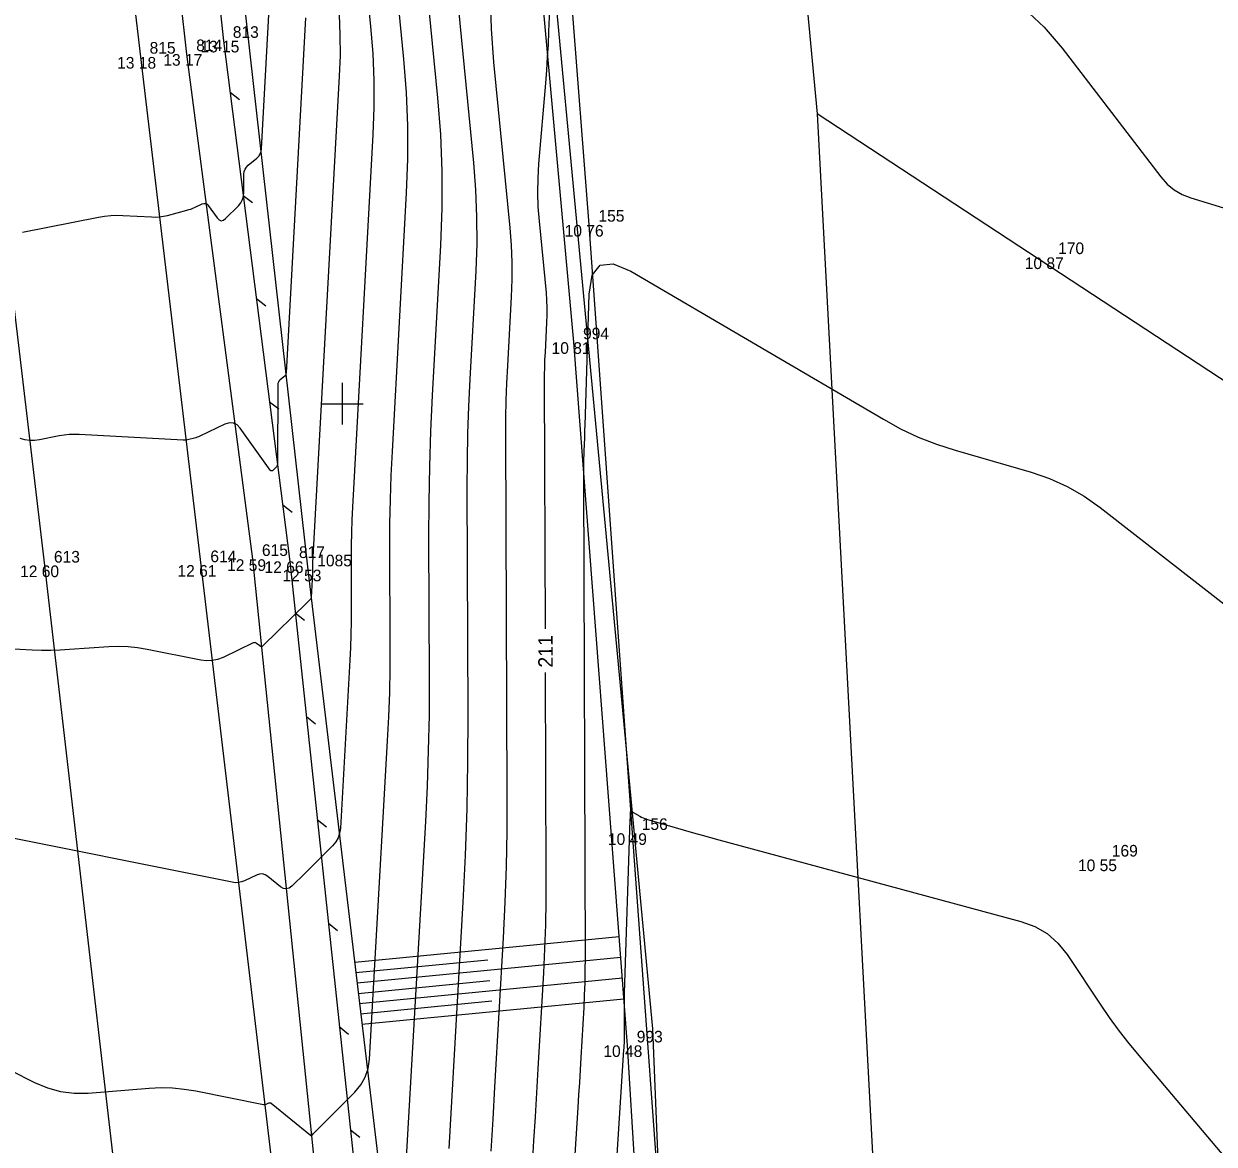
# Model space of a CAD drawing. Extents: x -711234 to -710007, y -1026313 to -1025448.
# Drawn here: x -710907.65 to -710879.04, y -1025892.81 to -1025865.86 of the extents above; entities that cross this region are included whole.
import ezdxf

# ---------------------------------------------------------------- set-up
doc = ezdxf.new("R2010")
doc.units = 0
for name, color, linetype in [('Ex_Contour Labels', 7, 'Continuous'), ('Ex_Major Contours', 7, 'Continuous'), ('Ex_Minor Contours', 7, 'Continuous'), ('Z_body', 7, 'Continuous'), ('Z_body_cisla', 7, 'Continuous'), ('Z_body_vysky_redukovane', 7, 'Continuous'), ('Z_hektometricka_sit', 7, 'Continuous'), ('Z_hrany_paty', 7, 'Continuous'), ('Z_katastr_hranice', 7, 'Continuous'), ('Z_komunikace', 7, 'Continuous'), ('Z_pole_rozhranni', 7, 'Continuous'), ('Z_svodidla', 7, 'Continuous'), ('Z_svodidla_znacky', 7, 'Continuous'), ('Z_technicke_srafy', 7, 'Continuous'), ('Z_vdz12_plna', 7, 'Continuous'), ('Z_vdz12_prerusovana', 7, 'Continuous'), ('Z_vdz25_plna', 7, 'Continuous')]:
    doc.layers.add(name, color=color, linetype=linetype)

# ---------------------------------------------------------------- blocks, each defined once
blk = doc.blocks.new('POINT_DISPLAY')
blk.add_line((0, 0), (0, 0))
blk = doc.blocks.new('Z529')
blk.add_line((0, 0), (0.2, 0.2))

msp = doc.modelspace()

# ---------------------------------------------------------------- linework, layer by layer
at = {"layer": 'Ex_Major Contours'}
for points in [[(-710909.71, -1025890.152), (-710907.396, -1025891.324), (-710907.088, -1025891.455), (-710906.771, -1025891.541), (-710906.445, -1025891.582), (-710906.11, -1025891.577), (-710904.638, -1025891.46), (-710904.356, -1025891.447), (-710904.076, -1025891.454), (-710903.797, -1025891.481), (-710903.52, -1025891.527), (-710901.891, -1025891.854), (-710901.874, -1025891.856), (-710901.858, -1025891.855), (-710901.841, -1025891.852), (-710901.826, -1025891.845), (-710901.762, -1025891.815), (-710901.747, -1025891.81), (-710901.732, -1025891.81), (-710901.718, -1025891.814), (-710901.704, -1025891.822), (-710900.759, -1025892.591), (-710900.751, -1025892.596), (-710900.742, -1025892.598), (-710900.734, -1025892.595), (-710900.726, -1025892.589), (-710900.687, -1025892.551), (-710900.671, -1025892.535), (-710900.663, -1025892.527), (-710899.698, -1025891.555), (-710899.553, -1025891.382), (-710899.446, -1025891.193), (-710899.376, -1025890.986), (-710899.344, -1025890.763), (-710898.908, -1025883.107), (-710898.879, -1025882.527), (-710898.859, -1025881.947), (-710898.848, -1025881.367), (-710898.846, -1025880.787), (-710898.854, -1025878.465), (-710898.852, -1025877.885), (-710898.841, -1025877.305), (-710898.822, -1025876.725), (-710898.794, -1025876.145), (-710898.452, -1025869.926), (-710898.423, -1025869.121), (-710898.425, -1025868.317), (-710898.457, -1025867.513), (-710898.52, -1025866.711), (-710898.947, -1025862.338)], [(-710907.682, -1025870.871), (-710905.856, -1025870.512), (-710905.711, -1025870.488), (-710905.566, -1025870.474), (-710905.42, -1025870.468), (-710905.273, -1025870.471), (-710904.587, -1025870.508), (-710904.49, -1025870.51), (-710904.394, -1025870.504), (-710904.298, -1025870.49), (-710904.203, -1025870.469), (-710903.733, -1025870.346), (-710903.685, -1025870.332), (-710903.638, -1025870.317), (-710903.592, -1025870.299), (-710903.547, -1025870.278), (-710903.367, -1025870.194), (-710903.324, -1025870.18), (-710903.285, -1025870.182), (-710903.25, -1025870.199), (-710903.219, -1025870.232), (-710903.004, -1025870.53), (-710902.958, -1025870.579), (-710902.909, -1025870.597), (-710902.857, -1025870.587), (-710902.804, -1025870.546), (-710902.496, -1025870.237), (-710902.438, -1025870.166), (-710902.396, -1025870.089), (-710902.371, -1025870.005), (-710902.363, -1025869.914), (-710902.362, -1025869.482), (-710902.355, -1025869.418), (-710902.335, -1025869.36), (-710902.303, -1025869.308), (-710902.258, -1025869.262), (-710902.051, -1025869.09), (-710902.005, -1025869.044), (-710901.971, -1025868.992), (-710901.949, -1025868.934), (-710901.94, -1025868.87), (-710901.689, -1025864.314)], [(-710895.115, -1025880.412), (-710895.136, -1025874.484), (-710895.135, -1025874.304), (-710895.132, -1025874.124), (-710895.126, -1025873.945), (-710895.117, -1025873.765), (-710895.078, -1025873.048), (-710895.071, -1025872.869), (-710895.072, -1025872.689), (-710895.079, -1025872.51), (-710895.093, -1025872.331), (-710895.261, -1025870.612), (-710895.287, -1025870.265), (-710895.297, -1025869.919), (-710895.292, -1025869.572), (-710895.271, -1025869.226), (-710895.109, -1025867.289), (-710895.084, -1025866.978), (-710895.063, -1025866.667), (-710895.045, -1025866.357), (-710895.03, -1025866.046), (-710894.978, -1025864.801)], [(-710883.607, -1025865.495), (-710883.129, -1025865.943), (-710882.697, -1025866.447), (-710880.323, -1025869.545), (-710880.172, -1025869.715), (-710880.001, -1025869.855), (-710879.81, -1025869.966), (-710879.599, -1025870.048), (-710878.714, -1025870.318)], [(-710895.427, -1025893.301), (-710895.391, -1025892.724), (-710895.356, -1025892.147), (-710895.321, -1025891.569), (-710895.288, -1025890.992), (-710895.156, -1025888.683), (-710895.128, -1025888.105), (-710895.108, -1025887.528), (-710895.097, -1025886.95), (-710895.095, -1025886.372), (-710895.112, -1025881.462)]]:
    msp.add_lwpolyline(points, dxfattribs=at)
at = {"layer": 'Ex_Minor Contours'}
for points in [[(-710897.432, -1025892.913), (-710897.095, -1025886.99), (-710897.039, -1025885.864), (-710897, -1025884.737), (-710896.979, -1025883.61), (-710896.974, -1025882.482), (-710896.993, -1025877.019), (-710896.99, -1025876.367), (-710896.978, -1025875.715), (-710896.957, -1025875.063), (-710896.926, -1025874.411), (-710896.782, -1025871.805), (-710896.759, -1025871.154), (-710896.76, -1025870.503), (-710896.786, -1025869.853), (-710896.838, -1025869.203), (-710897.575, -1025861.661)], [(-710898.261, -1025861.999), (-710897.71, -1025867.64), (-710897.64, -1025868.525), (-710897.605, -1025869.41), (-710897.603, -1025870.297), (-710897.635, -1025871.184), (-710897.834, -1025874.804), (-710897.875, -1025875.657), (-710897.903, -1025876.51), (-710897.918, -1025877.364), (-710897.922, -1025878.218), (-710897.91, -1025881.634), (-710897.913, -1025882.488), (-710897.93, -1025883.342), (-710897.959, -1025884.195), (-710898.001, -1025885.048), (-710898.533, -1025894.389)], [(-710899.634, -1025862.676), (-710899.316, -1025865.926), (-710899.265, -1025866.574), (-710899.239, -1025867.223), (-710899.238, -1025867.873), (-710899.261, -1025868.523), (-710899.754, -1025877.487), (-710899.769, -1025877.793), (-710899.779, -1025878.1), (-710899.785, -1025878.406), (-710899.786, -1025878.713), (-710899.782, -1025879.939), (-710899.783, -1025880.246), (-710899.789, -1025880.552), (-710899.799, -1025880.859), (-710899.815, -1025881.165), (-710900.045, -1025885.21), (-710900.062, -1025885.328), (-710900.099, -1025885.437), (-710900.155, -1025885.537), (-710900.232, -1025885.628), (-710900.604, -1025886.003), (-710900.677, -1025886.076), (-710900.751, -1025886.149), (-710900.824, -1025886.222), (-710900.898, -1025886.295), (-710901.212, -1025886.602), (-710901.278, -1025886.651), (-710901.346, -1025886.669), (-710901.415, -1025886.657), (-710901.485, -1025886.614), (-710901.789, -1025886.367), (-710901.852, -1025886.327), (-710901.918, -1025886.309), (-710901.986, -1025886.311), (-710902.057, -1025886.335), (-710902.345, -1025886.472), (-710902.418, -1025886.5), (-710902.492, -1025886.516), (-710902.568, -1025886.519), (-710902.646, -1025886.509), (-710908.814, -1025885.27)], [(-710896.421, -1025892.972), (-710896.375, -1025892.204), (-710896.331, -1025891.437), (-710896.126, -1025887.843), (-710896.084, -1025886.988), (-710896.054, -1025886.132), (-710896.038, -1025885.277), (-710896.034, -1025884.42), (-710896.064, -1025875.751), (-710896.063, -1025875.335), (-710896.055, -1025874.92), (-710896.041, -1025874.504), (-710896.021, -1025874.088), (-710895.93, -1025872.427), (-710895.915, -1025872.011), (-710895.916, -1025871.596), (-710895.933, -1025871.182), (-710895.965, -1025870.767), (-710896.355, -1025866.785), (-710896.415, -1025865.983), (-710896.438, -1025865.18)], [(-710900.074, -1025865.635), (-710900.054, -1025866.13), (-710900.053, -1025866.624), (-710900.07, -1025867.12), (-710900.715, -1025878.829), (-710900.716, -1025878.862), (-710900.717, -1025878.895), (-710900.718, -1025878.927), (-710900.718, -1025878.96), (-710900.718, -1025879.092), (-710900.718, -1025879.125), (-710900.718, -1025879.157), (-710900.72, -1025879.19), (-710900.721, -1025879.223), (-710900.746, -1025879.656), (-710900.748, -1025879.669), (-710900.752, -1025879.681), (-710900.758, -1025879.691), (-710900.766, -1025879.701), (-710900.803, -1025879.739), (-710900.821, -1025879.757), (-710900.84, -1025879.776), (-710901.909, -1025880.821), (-710901.927, -1025880.834), (-710901.944, -1025880.839), (-710901.963, -1025880.836), (-710901.981, -1025880.824), (-710902.057, -1025880.763), (-710902.076, -1025880.751), (-710902.096, -1025880.745), (-710902.117, -1025880.746), (-710902.138, -1025880.753), (-710902.865, -1025881.099), (-710902.995, -1025881.149), (-710903.127, -1025881.176), (-710903.263, -1025881.182), (-710903.401, -1025881.165), (-710904.691, -1025880.906), (-710904.919, -1025880.868), (-710905.149, -1025880.845), (-710905.38, -1025880.838), (-710905.612, -1025880.847), (-710906.556, -1025880.913), (-710906.781, -1025880.926), (-710907.005, -1025880.931), (-710907.23, -1025880.93), (-710907.454, -1025880.922), (-710908.353, -1025880.875)], [(-710900.88, -1025865.717), (-710901.349, -1025874.253), (-710901.354, -1025874.283), (-710901.364, -1025874.31), (-710901.38, -1025874.334), (-710901.401, -1025874.356), (-710901.498, -1025874.436), (-710901.52, -1025874.458), (-710901.535, -1025874.482), (-710901.544, -1025874.509), (-710901.547, -1025874.539), (-710901.552, -1025876.439), (-710901.554, -1025876.464), (-710901.561, -1025876.487), (-710901.573, -1025876.508), (-710901.588, -1025876.527), (-710901.661, -1025876.6), (-710901.679, -1025876.614), (-710901.696, -1025876.617), (-710901.712, -1025876.611), (-710901.728, -1025876.595), (-710902.452, -1025875.588), (-710902.529, -1025875.507), (-710902.616, -1025875.464), (-710902.712, -1025875.46), (-710902.818, -1025875.493), (-710903.422, -1025875.778), (-710903.454, -1025875.792), (-710903.486, -1025875.804), (-710903.519, -1025875.816), (-710903.553, -1025875.825), (-710903.688, -1025875.861), (-710903.722, -1025875.868), (-710903.757, -1025875.873), (-710903.791, -1025875.875), (-710903.826, -1025875.875), (-710906.321, -1025875.74), (-710906.442, -1025875.737), (-710906.562, -1025875.742), (-710906.681, -1025875.754), (-710906.8, -1025875.774), (-710907.274, -1025875.867), (-710907.393, -1025875.882), (-710907.51, -1025875.882), (-710907.626, -1025875.866), (-710907.741, -1025875.835)], [(-710894.829, -1025899.828), (-710894.328, -1025891.921), (-710894.309, -1025891.621), (-710894.29, -1025891.321), (-710894.273, -1025891.022), (-710894.255, -1025890.722), (-710894.187, -1025889.523), (-710894.172, -1025889.223), (-710894.162, -1025888.923), (-710894.156, -1025888.623), (-710894.155, -1025888.323), (-710894.195, -1025876.81), (-710894.195, -1025876.702), (-710894.194, -1025876.595), (-710894.191, -1025876.487), (-710894.188, -1025876.38), (-710894.174, -1025875.949), (-710894.171, -1025875.842), (-710894.168, -1025875.734), (-710894.164, -1025875.627), (-710894.161, -1025875.519), (-710894.065, -1025872.365), (-710893.99, -1025871.909), (-710893.798, -1025871.665), (-710893.489, -1025871.632), (-710893.062, -1025871.811), (-710886.992, -1025875.374), (-710886.577, -1025875.6), (-710886.151, -1025875.8), (-710885.713, -1025875.972), (-710885.263, -1025876.118), (-710883.441, -1025876.646), (-710882.996, -1025876.798), (-710882.571, -1025876.99), (-710882.166, -1025877.222), (-710881.782, -1025877.493), (-710875.472, -1025882.413)], [(-710893.982, -1025902.415), (-710893.228, -1025890.54), (-710893.225, -1025890.496), (-710893.223, -1025890.452), (-710893.218, -1025890.363), (-710893.216, -1025890.341), (-710893.216, -1025890.318), (-710893.215, -1025890.296), (-710893.215, -1025890.274), (-710893.217, -1025889.633), (-710893.217, -1025889.519), (-710893.216, -1025889.405), (-710893.214, -1025889.291), (-710893.211, -1025889.177), (-710893.075, -1025885.004), (-710893.073, -1025884.939), (-710893.07, -1025884.831), (-710893.067, -1025884.814), (-710893.06, -1025884.804), (-710893.048, -1025884.803), (-710893.031, -1025884.81), (-710892.842, -1025884.921), (-710892.804, -1025884.942), (-710892.764, -1025884.961), (-710892.724, -1025884.976), (-710892.682, -1025884.99), (-710891.552, -1025885.318), (-710891.349, -1025885.376), (-710891.146, -1025885.433), (-710890.943, -1025885.489), (-710890.74, -1025885.545), (-710883.684, -1025887.449), (-710883.351, -1025887.57), (-710883.055, -1025887.744), (-710882.797, -1025887.969), (-710882.576, -1025888.247), (-710881.767, -1025889.461), (-710881.56, -1025889.762), (-710881.346, -1025890.056), (-710881.123, -1025890.345), (-710880.892, -1025890.627), (-710876.471, -1025895.869)]]:
    msp.add_lwpolyline(points, dxfattribs=at)
at = {"layer": 'Z_hektometricka_sit'}
for p, q in [((-710900, -1025874.5), (-710900, -1025875.5)), ((-710900.5, -1025875), (-710899.5, -1025875))]:
    msp.add_line(p, q, dxfattribs=at)
at = {"layer": 'Z_hrany_paty'}
for p, q in [((-710894.43, -1025873.52), (-710895.98, -1025856.57)), ((-710902.66, -1025862.63), (-710900.83, -1025878.99)), ((-710893.14, -1025890.43), (-710894.43, -1025873.52)), ((-710900.83, -1025878.99), (-710898.93, -1025894.92)), ((-710892.06, -1025908.49), (-710893.14, -1025890.43))]:
    msp.add_line(p, q, dxfattribs=at)
at = {"layer": 'Z_katastr_hranice'}
for points in [[(-710889, -1025970.31), (-710889.68, -1025960.38), (-710892.53, -1025890.03), (-710898.37, -1025828.05), (-710905.02, -1025776.43), (-710911.59, -1025735.63)], [(-710900.43, -1025767.22), (-710899.08, -1025775.57), (-710892.41, -1025827.39), (-710888.58, -1025868.03)], [(-710382.551, -1026200.162), (-710414.43, -1026179.24), (-710572.48, -1026075.5), (-710730.53, -1025971.77), (-710888.58, -1025868.03)], [(-710888.58, -1025868.03), (-710883.69, -1025960.07), (-710882.89, -1025972.98)]]:
    msp.add_lwpolyline(points, dxfattribs=at)
at = {"layer": 'Z_komunikace'}
for p, q in [((-710905.46, -1025851.72), (-710903.74, -1025866.59)), ((-710903.74, -1025866.59), (-710902.16, -1025878.74)), ((-710902.16, -1025878.74), (-710900.67, -1025893.31))]:
    msp.add_line(p, q, dxfattribs=at)
at = {"layer": 'Z_pole_rozhranni'}
for p, q in [((-710895.24, -1025855.79), (-710894.07, -1025870.7)), ((-710894.07, -1025870.7), (-710893.03, -1025885.33)), ((-710893.03, -1025885.33), (-710891.98, -1025899.73))]:
    msp.add_line(p, q, dxfattribs=at)
at = {"layer": 'Z_svodidla'}
for p, q in [((-710904.43, -1025852.27), (-710902.85, -1025866.27)), ((-710902.85, -1025866.27), (-710901.26, -1025878.79)), ((-710901.26, -1025878.79), (-710899.25, -1025897.61))]:
    msp.add_line(p, q, dxfattribs=at)
at = {"layer": 'Z_technicke_srafy'}
for p, q in [((-710899.7, -1025888.43), (-710893.34, -1025887.81)), ((-710899.67, -1025888.68), (-710896.5, -1025888.37)), ((-710899.64, -1025888.93), (-710893.3, -1025888.31)), ((-710899.62, -1025889.18), (-710896.45, -1025888.87)), ((-710899.59, -1025889.42), (-710893.26, -1025888.81)), ((-710899.53, -1025889.92), (-710893.23, -1025889.31)), ((-710899.56, -1025889.67), (-710896.4, -1025889.36))]:
    msp.add_line(p, q, dxfattribs=at)
at = {"layer": 'Z_vdz12_plna'}
msp.add_line((-710907.16, -1025878.89), (-710905.45, -1025893.65), dxfattribs=at)
at = {"layer": 'Z_vdz12_prerusovana'}
msp.add_line((-710908.52, -1025867.38), (-710907.16, -1025878.89), dxfattribs=at)
at = {"layer": 'Z_vdz25_plna'}
for p, q in [((-710906.58, -1025851.89), (-710904.85, -1025866.66)), ((-710904.85, -1025866.66), (-710903.4, -1025878.88)), ((-710903.4, -1025878.88), (-710901.68, -1025893.35))]:
    msp.add_line(p, q, dxfattribs=at)

# ---------------------------------------------------------------- block references
at = {"layer": 'Z_body'}
for p in [(-710902.85, -1025866.27), (-710904.85, -1025866.66), (-710903.74, -1025866.59), (-710894.07, -1025870.7), (-710883.01, -1025871.48), (-710894.43, -1025873.52), (-710907.16, -1025878.89), (-710903.4, -1025878.88), (-710902.16, -1025878.74), (-710901.26, -1025878.79), (-710900.83, -1025878.99), (-710893.03, -1025885.33), (-710881.73, -1025885.96), (-710893.14, -1025890.43)]:
    msp.add_blockref('POINT_DISPLAY', p, dxfattribs=at)
at = {"layer": 'Z_svodidla_znacky'}
for p, rotation in [((-710902.69, -1025867.51), -82.8), ((-710902.38, -1025869.99), -82.8), ((-710902.06, -1025872.47), -82.8), ((-710901.75, -1025874.95), -82.8), ((-710901.43, -1025877.43), -82.8), ((-710901.13, -1025880.03), -83.89999999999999), ((-710900.86, -1025882.52), -83.89999999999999), ((-710900.6, -1025885), -83.89999999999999), ((-710900.33, -1025887.49), -83.89999999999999), ((-710900.07, -1025889.98), -83.89999999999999), ((-710899.8, -1025892.46), -83.89999999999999)]:
    msp.add_blockref('Z529', p, dxfattribs=dict(at, rotation=rotation))

# ---------------------------------------------------------------- texts
at = {"layer": 'Ex_Contour Labels'}
msp.add_text('211', height=0.35, rotation=90.1981, dxfattribs=at).set_placement((-710894.937, -1025881.345))
at = {"layer": 'Z_body_cisla'}
for s, p in [('813', (-710902.63, -1025866.2)), ('815', (-710904.63, -1025866.58)), ('814', (-710903.51, -1025866.52)), ('155', (-710893.84, -1025870.62)), ('170', (-710882.79, -1025871.4)), ('994', (-710894.21, -1025873.45)), ('615', (-710901.93, -1025878.66)), ('817', (-710901.04, -1025878.71)), ('613', (-710906.93, -1025878.82)), ('614', (-710903.17, -1025878.81)), ('1085', (-710900.6, -1025878.91)), ('156', (-710892.8, -1025885.25)), ('169', (-710881.5, -1025885.89)), ('993', (-710892.92, -1025890.36))]:
    msp.add_text(s, height=0.28, dxfattribs=at).set_placement(p)
at = {"layer": 'Z_body_vysky_redukovane'}
for s, p in [('13 15', (-710903.41, -1025866.55)), ('13 18', (-710905.41, -1025866.94)), ('13 17', (-710904.3, -1025866.87)), ('10 76', (-710894.653, -1025870.98)), ('10 87', (-710883.593, -1025871.76)), ('10 81', (-710894.967, -1025873.8)), ('12 60', (-710907.743, -1025879.17)), ('12 61', (-710903.96, -1025879.16)), ('12 59', (-710902.767, -1025879.02)), ('12 66', (-710901.867, -1025879.07)), ('12 53', (-710901.437, -1025879.27)), ('10 49', (-710893.613, -1025885.61)), ('10 55', (-710882.313, -1025886.24)), ('10 48', (-710893.723, -1025890.71))]:
    msp.add_text(s, height=0.28, dxfattribs=at).set_placement(p)

doc.saveas('drawing.dxf')
